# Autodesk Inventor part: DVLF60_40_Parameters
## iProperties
Created: 2010-03
Part Number: DVLF60_40_Parameters
Document SubType Name: Modeling
Designer: TB
Density: 1 g/cm^3
Slaglengde: 100.000 mm
Vinkel_Plussport: 0.00 deg
Vinkel_Minusport: 0.00 deg
Forlengelse_rør: 0.000 mm
Author: TB
